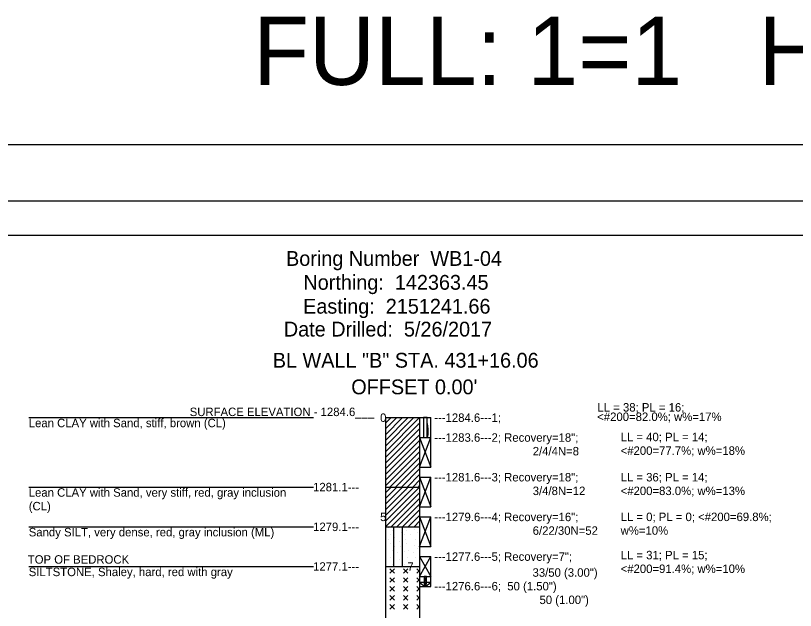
# Model space of a CAD drawing. Extents: x 7 to 126, y 24 to 56.
# Drawn here: x 96.51 to 107.93, y 47.51 to 56.22 of the extents above; entities that cross this region are included whole.
import ezdxf

# ---------------------------------------------------------------- set-up
doc = ezdxf.new("R2010")
doc.units = 0
for name, color, linetype in [('S', 7, 'Continuous'), ('SHT_Plot_Shape_Full', 7, 'Continuous'), ('SHT_Plot_Shape_Half', 7, 'Continuous'), ('SHT_Sheet_Border', 7, 'Continuous')]:
    doc.layers.add(name, color=color, linetype=linetype)

# ---------------------------------------------------------------- blocks, each defined once
blk = doc.blocks.new('POINT_DISPLAY')
blk.add_line((0, 0), (0, 0))

msp = doc.modelspace()

# ---------------------------------------------------------------- linework, layer by layer
for points in [[(96.704, 50.334), (100.871, 50.334)], [(101.925, 50.251), (102.009, 50.334)], [(101.925, 50.168), (102.092, 50.334)], [(101.925, 50.084), (102.175, 50.334)], [(101.925, 50.001), (102.259, 50.334)], [(101.925, 49.918), (102.342, 50.334)], [(101.925, 49.834), (102.425, 50.334)], [(101.925, 50.334), (101.925, 39.288)], [(101.925, 50.334), (102.425, 50.334)], [(101.925, 49.751), (102.425, 50.251)], [(102.425, 50.334), (102.592, 50.334)], [(102.425, 50.334), (102.425, 39.288)], [(102.592, 50.044), (102.592, 50.334)], [(101.925, 49.668), (102.425, 50.168)], [(101.925, 49.584), (102.425, 50.084)], [(101.925, 49.501), (102.425, 50.001)], [(102.425, 50.044), (102.592, 50.044)], [(102.425, 50.044), (102.592, 49.608)], [(102.425, 49.608), (102.592, 50.044)], [(102.425, 50.044), (102.592, 50.044)], [(102.592, 49.608), (102.592, 50.044)], [(101.925, 49.418), (102.425, 49.918)], [(101.925, 49.334), (102.425, 49.834)], [(101.991, 49.317), (102.425, 49.751)], [(102.074, 49.317), (102.425, 49.668)], [(102.158, 49.317), (102.425, 49.584)], [(102.425, 49.608), (102.592, 49.608)], [(102.241, 49.317), (102.425, 49.501)], [(102.425, 49.462), (102.592, 49.026)], [(102.425, 49.026), (102.592, 49.462)], [(102.425, 49.462), (102.592, 49.462)], [(102.592, 49.026), (102.592, 49.462)], [(96.704, 49.317), (100.871, 49.317)], [(101.925, 49.317), (102.425, 49.317)], [(101.925, 49.234), (102.009, 49.317)], [(101.925, 49.15), (102.092, 49.317)], [(101.925, 49.067), (102.175, 49.317)], [(101.925, 48.984), (102.259, 49.317)], [(101.925, 48.9), (102.342, 49.317)], [(101.925, 48.817), (102.425, 49.317)], [(102.324, 49.317), (102.425, 49.418)], [(102.408, 49.317), (102.425, 49.334)], [(101.927, 48.735), (102.425, 49.234)], [(102.01, 48.735), (102.425, 49.15)], [(102.094, 48.735), (102.425, 49.067)], [(102.177, 48.735), (102.425, 48.984)], [(102.425, 49.026), (102.592, 49.026)], [(102.26, 48.735), (102.425, 48.9)], [(102.425, 48.881), (102.592, 48.445)], [(102.425, 48.445), (102.592, 48.881)], [(102.425, 48.881), (102.592, 48.881)], [(102.592, 48.445), (102.592, 48.881)], [(102.344, 48.735), (102.425, 48.817)], [(96.704, 48.735), (100.871, 48.735)], [(101.925, 48.735), (102.425, 48.735)], [(102.05, 48.154), (102.05, 48.735)], [(102.175, 48.154), (102.175, 48.735)], [(102.425, 48.445), (102.592, 48.445)], [(102.425, 48.299), (102.592, 48.009)], [(102.425, 48.009), (102.592, 48.299)], [(102.425, 48.299), (102.592, 48.299)], [(102.592, 48.009), (102.592, 48.299)], [(96.704, 48.154), (100.871, 48.154)], [(101.925, 48.154), (102.425, 48.154)], [(102.056, 48.121), (101.991, 48.056)], [(101.991, 48.121), (102.056, 48.056)], [(102.253, 48.121), (102.188, 48.056)], [(102.188, 48.121), (102.253, 48.056)], [(102.385, 48.121), (102.425, 48.081)], [(102.425, 48.096), (102.385, 48.056)], [(102.056, 47.99), (101.991, 47.924)], [(101.991, 47.99), (102.056, 47.924)], [(102.253, 47.99), (102.188, 47.924)], [(102.188, 47.99), (102.253, 47.924)], [(102.385, 47.99), (102.425, 47.949)], [(102.425, 47.965), (102.385, 47.924)], [(102.425, 48.009), (102.592, 48.009)], [(102.425, 48.009), (102.592, 48.009)], [(102.592, 47.863), (102.592, 48.009)], [(102.056, 47.859), (101.991, 47.793)], [(101.991, 47.859), (102.056, 47.793)], [(102.253, 47.859), (102.188, 47.793)], [(102.188, 47.859), (102.253, 47.793)], [(102.385, 47.859), (102.425, 47.818)], [(102.425, 47.834), (102.385, 47.793)], [(102.425, 47.863), (102.592, 47.863)], [(102.056, 47.728), (101.991, 47.662)], [(101.991, 47.728), (102.056, 47.662)], [(102.253, 47.728), (102.188, 47.662)], [(102.188, 47.728), (102.253, 47.662)], [(102.385, 47.728), (102.425, 47.687)], [(102.425, 47.703), (102.385, 47.662)], [(102.056, 47.596), (101.991, 47.531)], [(101.991, 47.596), (102.056, 47.531)], [(102.253, 47.596), (102.188, 47.531)], [(102.188, 47.596), (102.253, 47.531)], [(102.385, 47.596), (102.425, 47.556)], [(102.425, 47.571), (102.385, 47.531)]]:
    msp.add_lwpolyline(points)
for points in [[(102.484, 50.334), (102.484, 50.044), (102.534, 50.044), (102.534, 50.334)], [(102.548, 50.168), (102.542, 50.209), (102.534, 50.249), (102.548, 50.168)], [(102.534, 50.249), (102.534, 50.044), (102.548, 50.168), (102.534, 50.249)], [(102.534, 50.044), (102.548, 50.084), (102.548, 50.168), (102.534, 50.044)], [(102.548, 50.084), (102.55, 50.126), (102.548, 50.168), (102.548, 50.084)], [(102.534, 50.044), (102.542, 50.044), (102.548, 50.084), (102.534, 50.044)], [(102.492, 47.922), (102.525, 47.922), (102.525, 48.009), (102.492, 47.922)], [(102.492, 47.922), (102.525, 48.009), (102.492, 48.009), (102.492, 47.922)], [(102.492, 47.922), (102.425, 47.922), (102.509, 47.863), (102.492, 47.922)], [(102.492, 47.922), (102.509, 47.863), (102.525, 47.922), (102.492, 47.922)], [(102.509, 47.863), (102.592, 47.922), (102.525, 47.922), (102.509, 47.863)]]:
    msp.add_lwpolyline(points, close=True)
at = {"layer": 'SHT_Plot_Shape_Full'}
msp.add_lwpolyline([(89.683, 54.332), (125.683, 54.332), (125.683, 30.332), (89.683, 30.332)], close=True, dxfattribs=at)
at = {"layer": 'SHT_Plot_Shape_Half'}
msp.add_lwpolyline([(91.321, 53.507), (125.321, 53.507), (125.321, 31.507), (91.321, 31.507)], close=True, dxfattribs=at)
at = {"layer": 'SHT_Sheet_Border'}
msp.add_lwpolyline([(93.271, 53.007), (124.771, 53.007), (124.771, 32.007), (93.271, 32.007)], close=True, dxfattribs=at)

# ---------------------------------------------------------------- block references
at = {"xscale": 0.01, "yscale": 0.01}
for p in [(101.931, 50.251), (101.964, 50.318), (102.031, 50.284), (102.131, 50.318), (102.154, 50.254), (102.231, 50.284), (102.351, 50.301), (102.398, 50.251), (101.964, 50.151), (101.998, 50.218), (102.064, 50.184), (102.131, 50.118), (102.198, 50.218), (102.215, 50.142), (102.298, 50.218), (102.364, 50.151), (101.931, 50.018), (101.998, 50.084), (102.064, 50.051), (102.149, 50.04), (102.231, 50.084), (102.349, 50.066), (102.398, 50.018), (101.998, 49.884), (102.031, 49.984), (102.098, 49.951), (102.164, 49.918), (102.201, 49.971), (102.243, 49.884), (102.264, 49.984), (102.331, 49.951), (102.364, 49.884), (101.931, 49.818), (102.031, 49.784), (102.131, 49.851), (102.198, 49.784), (102.298, 49.818), (101.964, 49.751), (102.164, 49.718), (102.264, 49.684), (102.364, 49.751), (101.931, 49.584), (101.964, 49.651), (101.998, 49.551), (102.031, 49.618), (102.131, 49.651), (102.154, 49.587), (102.198, 49.551), (102.231, 49.618), (102.298, 49.551), (102.351, 49.634), (102.398, 49.584), (101.964, 49.484), (102.064, 49.518), (102.131, 49.451), (102.215, 49.475), (102.364, 49.484), (101.931, 49.351), (101.998, 49.418), (102.031, 49.318), (102.064, 49.384), (102.149, 49.374), (102.231, 49.418), (102.264, 49.318), (102.349, 49.399), (102.398, 49.351), (101.931, 49.234), (101.964, 49.3), (101.998, 49.2), (102.031, 49.267), (102.131, 49.3), (102.154, 49.237), (102.198, 49.2), (102.231, 49.267), (102.298, 49.2), (102.351, 49.284), (102.398, 49.234), (101.964, 49.134), (102.064, 49.167), (102.131, 49.1), (102.215, 49.124), (102.364, 49.134), (101.931, 49), (101.998, 49.067), (102.064, 49.034), (102.149, 49.023), (102.231, 49.067), (102.349, 49.049), (102.398, 49), (101.998, 48.867), (102.031, 48.967), (102.098, 48.934), (102.164, 48.9), (102.201, 48.953), (102.243, 48.867), (102.264, 48.967), (102.331, 48.934), (102.364, 48.867), (101.931, 48.8), (102.031, 48.767), (102.131, 48.834), (102.198, 48.767), (102.298, 48.8), (101.931, 48.652), (101.964, 48.719), (102.031, 48.685), (102.131, 48.719), (102.154, 48.655), (102.231, 48.685), (102.351, 48.702), (102.398, 48.652), (101.964, 48.552), (101.998, 48.619), (102.064, 48.585), (102.131, 48.519), (102.198, 48.619), (102.215, 48.543), (102.298, 48.619), (102.364, 48.552), (101.931, 48.419), (101.998, 48.485), (102.064, 48.452), (102.149, 48.442), (102.231, 48.485), (102.349, 48.467), (102.398, 48.419), (101.998, 48.285), (102.031, 48.385), (102.098, 48.352), (102.164, 48.319), (102.201, 48.372), (102.243, 48.285), (102.264, 48.385), (102.331, 48.352), (102.364, 48.285), (101.931, 48.219), (102.031, 48.185), (102.131, 48.252), (102.198, 48.185), (102.298, 48.219)]:
    msp.add_blockref('POINT_DISPLAY', p, dxfattribs=at)

# ---------------------------------------------------------------- texts
for s, height, p in [('Boring Number  WB1-04', 0.217, (100.47, 52.557)), ('Northing:  142363.45', 0.217, (100.724, 52.207)), ('Easting:  2151241.66', 0.217, (100.72, 51.857)), ('Date Drilled:  5/26/2017', 0.217, (100.438, 51.522)), ('BL WALL "B" STA. 431+16.06', 0.217, (100.276, 51.066)), ("OFFSET 0.00'", 0.217, (101.425, 50.676)), ('SURFACE ELEVATION - 1284.6___', 0.124, (99.06, 50.357)), ('LL = 38; PL = 16;', 0.124, (105.029, 50.423)), ('0', 0.124, (101.847, 50.272)), ('---1284.6---1;', 0.124, (102.64, 50.272)), ('<#200=82.0%; w%=17%', 0.124, (105.025, 50.285)), ('Lean CLAY with Sand, stiff, brown (CL)', 0.124, (96.704, 50.194)), ('LL = 40; PL = 14;', 0.124, (105.368, 49.989)), ('---1283.6---2; Recovery=18";', 0.124, (102.64, 49.981)), ('2/4/4N=8', 0.124, (104.081, 49.781)), ('<#200=77.7%; w%=18%', 0.124, (105.368, 49.789)), ('---1281.6---3; Recovery=18";', 0.124, (102.64, 49.4)), ('LL = 36; PL = 14;', 0.124, (105.368, 49.4)), ('1281.1---', 0.124, (100.866, 49.255)), ('3/4/8N=12', 0.124, (104.081, 49.2)), ('<#200=83.0%; w%=13%', 0.124, (105.368, 49.2)), ('Lean CLAY with Sand, very stiff, red, gray inclusion', 0.124, (96.704, 49.176)), ('(CL)', 0.124, (96.704, 48.976)), ('5', 0.124, (101.847, 48.819)), ('---1279.6---4; Recovery=16";', 0.124, (102.64, 48.818)), ('LL = 0; PL = 0; <#200=69.8%;', 0.124, (105.368, 48.819)), ('1279.1---', 0.124, (100.866, 48.673)), ('6/22/30N=52', 0.124, (104.081, 48.618)), ('w%=10%', 0.124, (105.368, 48.619)), ('Sandy SILT, very dense, red, gray inclusion (ML)', 0.124, (96.704, 48.595)), ('TOP OF BEDROCK', 0.124, (96.69, 48.195)), ('---1277.6---5; Recovery=7";', 0.124, (102.64, 48.237)), ('LL = 31; PL = 15;', 0.124, (105.368, 48.259)), ('1277.1---', 0.124, (100.866, 48.092)), ('7', 0.124, (102.247, 48.092)), ('<#200=91.4%; w%=10%', 0.124, (105.368, 48.059)), ('SILTSTONE, Shaley, hard, red with gray', 0.124, (96.704, 48.013)), ('33/50 (3.00")', 0.124, (104.078, 48.004)), ('---1276.6---6;  50 (1.50")', 0.124, (102.64, 47.804)), ('50 (1.00")', 0.124, (104.18, 47.604))]:
    msp.add_text(s, height=height).set_placement(p)
at = {"layer": 'S'}
msp.add_text('FULL: 1=1   HALF: 1=2', height=1, dxfattribs=at).set_placement((99.989, 55.207))

doc.saveas('drawing.dxf')
